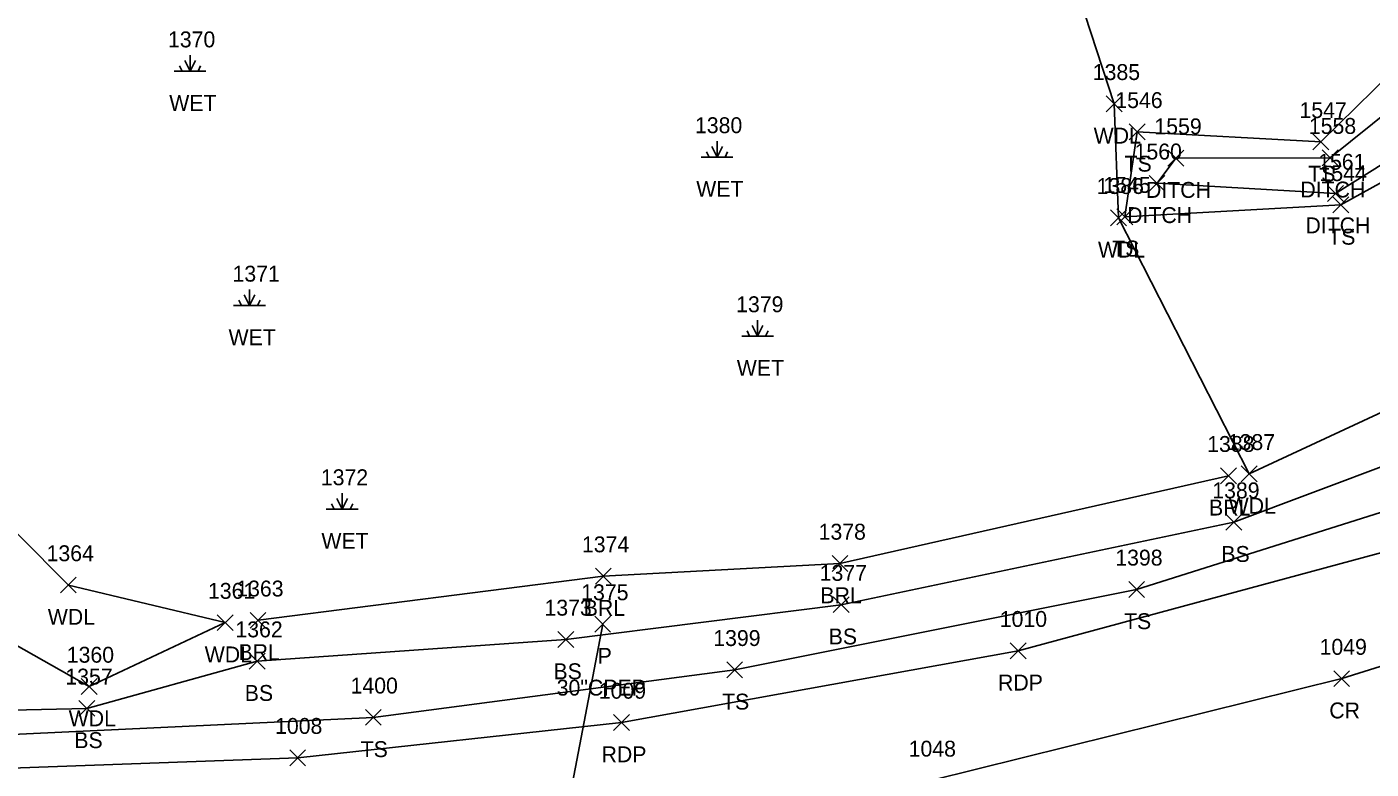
# Model space of a CAD drawing. Extents: x 1633660 to 1636532, y 388643 to 392631.
# Drawn here: x 1633906 to 1634075.1, y 388782.5 to 388875.9 of the extents above; entities that cross this region are included whole.
import ezdxf

# ---------------------------------------------------------------- set-up
doc = ezdxf.new("R2010")
doc.units = 0
for name, color, linetype in [('D_A', 7, 'Continuous'), ('D_C', 7, 'Continuous'), ('D_I', 7, 'Continuous'), ('D_TIC', 7, 'Continuous'), ('DCP', 7, 'Continuous'), ('DD', 7, 'Continuous'), ('L_A', 7, 'Continuous'), ('L_I', 7, 'Continuous'), ('L_TIC', 7, 'Continuous'), ('LABL', 7, 'Continuous'), ('LAWA', 7, 'Continuous'), ('LELB', 7, 'Continuous'), ('LWET', 7, 'Continuous'), ('P_A', 7, 'Continuous'), ('P_I', 7, 'Continuous'), ('P_TIC', 7, 'Continuous'), ('PET', 7, 'Continuous'), ('PRC', 7, 'Continuous')]:
    doc.layers.add(name, color=color, linetype=linetype)

msp = doc.modelspace()

# ---------------------------------------------------------------- linework, layer by layer
at = {"layer": 'D_TIC'}
for points in [[(1634049.51, 388858.37), (1634051.51, 388860.37)], [(1634051.51, 388858.37), (1634049.51, 388860.37)], [(1634068.93, 388858.42), (1634070.93, 388860.42)], [(1634070.93, 388858.42), (1634068.93, 388860.42)], [(1634047.14, 388855.2), (1634049.14, 388857.2)], [(1634049.14, 388855.2), (1634047.14, 388857.2)], [(1634069.58, 388853.91), (1634071.58, 388855.91)], [(1634071.58, 388853.91), (1634069.58, 388855.91)], [(1633977.41, 388799.74), (1633979.41, 388801.74)], [(1633979.41, 388799.74), (1633977.41, 388801.74)]]:
    msp.add_lwpolyline(points, dxfattribs=at)
at = {"layer": 'DCP'}
msp.add_lwpolyline([(1633978.41, 388800.74), (1633967.31, 388742.59)], dxfattribs=at)
at = {"layer": 'DD'}
msp.add_lwpolyline([(1634140.31, 388919.4), (1634122.83, 388893.99), (1634093.48, 388880.29), (1634083.12, 388870.01), (1634069.93, 388859.42), (1634050.51, 388859.37), (1634048.14, 388856.2), (1634070.58, 388854.91), (1634088.81, 388866.37), (1634110.94, 388881.74), (1634127.84, 388889.81), (1634143.36, 388916.71)], dxfattribs=at)
at = {"layer": 'L_TIC'}
for points in [[(1634041.75, 388865.2), (1634043.75, 388867.2)], [(1634043.75, 388865.2), (1634041.75, 388867.2)], [(1634044.65, 388861.67), (1634046.65, 388863.67)], [(1634046.65, 388861.67), (1634044.65, 388863.67)], [(1634067.75, 388860.41), (1634069.75, 388862.41)], [(1634069.75, 388860.41), (1634067.75, 388862.41)], [(1634070.27, 388852.48), (1634072.27, 388854.48)], [(1634072.27, 388852.48), (1634070.27, 388854.48)], [(1634042.29, 388850.86), (1634044.29, 388852.86)], [(1634044.29, 388850.86), (1634042.29, 388852.86)], [(1634043.09, 388850.99), (1634045.09, 388852.99)], [(1634045.09, 388850.99), (1634043.09, 388852.99)], [(1634056.14, 388818.4), (1634058.14, 388820.4)], [(1634058.14, 388818.4), (1634056.14, 388820.4)], [(1634058.73, 388818.64), (1634060.73, 388820.64)], [(1634060.73, 388818.64), (1634058.73, 388820.64)], [(1634056.79, 388812.56), (1634058.79, 388814.56)], [(1634058.79, 388812.56), (1634056.79, 388814.56)], [(1634007.26, 388807.36), (1634009.26, 388809.36)], [(1634009.26, 388807.36), (1634007.26, 388809.36)], [(1633977.49, 388805.77), (1633979.49, 388807.77)], [(1633979.49, 388805.77), (1633977.49, 388807.77)], [(1633910.2, 388804.65), (1633912.2, 388806.65)], [(1633912.2, 388804.65), (1633910.2, 388806.65)], [(1634044.58, 388804.1), (1634046.58, 388806.1)], [(1634046.58, 388804.1), (1634044.58, 388806.1)], [(1634007.4, 388802.18), (1634009.4, 388804.18)], [(1634009.4, 388802.18), (1634007.4, 388804.18)], [(1633929.93, 388799.92), (1633931.93, 388801.92)], [(1633931.93, 388799.92), (1633929.93, 388801.92)], [(1633934.06, 388800.21), (1633936.06, 388802.21)], [(1633936.06, 388800.21), (1633934.06, 388802.21)], [(1633972.78, 388797.8), (1633974.78, 388799.8)], [(1633974.78, 388797.8), (1633972.78, 388799.8)], [(1633933.95, 388795.07), (1633935.95, 388797.07)], [(1633935.95, 388795.07), (1633933.95, 388797.07)], [(1633994.02, 388793.98), (1633996.02, 388795.98)], [(1633996.02, 388793.98), (1633994.02, 388795.98)], [(1633912.82, 388791.88), (1633914.82, 388793.88)], [(1633914.82, 388791.88), (1633912.82, 388793.88)], [(1633912.51, 388789.13), (1633914.51, 388791.13)], [(1633914.51, 388789.13), (1633912.51, 388791.13)], [(1633948.56, 388788), (1633950.56, 388790)], [(1633950.56, 388788), (1633948.56, 388790)]]:
    msp.add_lwpolyline(points, dxfattribs=at)
at = {"layer": 'LABL'}
msp.add_lwpolyline([(1633935.06, 388801.21), (1633978.49, 388806.77), (1634008.26, 388808.36), (1634057.14, 388819.4)], dxfattribs=at)
at = {"layer": 'LAWA'}
for points in [[(1634029.51, 388906.75), (1634042.75, 388866.2), (1634043.29, 388851.86), (1634059.73, 388819.64), (1634086.07, 388831.91), (1634132.5, 388845.49), (1634141.64, 388844.49), (1634171.78, 388858.91), (1634210.32, 388873.4), (1634220.65, 388882.43), (1634241.67, 388885.4), (1634275.37, 388895.77), (1634312.68, 388911.32), (1634346.59, 388927.34), (1634362.7, 388937.8), (1634391.49, 388949.24), (1634419.55, 388956.24), (1634431.93, 388958.02)], [(1633871.87, 388818.29), (1633885.15, 388797.47), (1633895.12, 388803.46), (1633913.82, 388792.88), (1633930.93, 388800.92), (1633911.2, 388805.65), (1633898.58, 388818.29), (1633885.23, 388835.61), (1633885.66, 388866.72), (1633887.99, 388896.34)]]:
    msp.add_lwpolyline(points, dxfattribs=at)
at = {"layer": 'LELB'}
for points in [[(1634144.21, 388912.2), (1634135.78, 388896.22), (1634121.93, 388881.1), (1634093.91, 388866), (1634071.27, 388853.48), (1634044.09, 388851.99), (1634045.65, 388862.67), (1634068.75, 388861.41), (1634082.09, 388874.51), (1634092.19, 388884.76), (1634120.03, 388895.98), (1634133.03, 388917.32)], [(1633865.46, 388809.99), (1633877.4, 388789.31), (1633913.51, 388790.13), (1633934.95, 388796.07), (1633973.78, 388798.8), (1634008.4, 388803.18), (1634057.79, 388813.56), (1634087.95, 388824.89), (1634134.34, 388843.13)], [(1634140.78, 388840.91), (1634131.75, 388832.34), (1634088.08, 388818.52), (1634045.58, 388805.1), (1633995.02, 388794.98), (1633949.56, 388789), (1633902.34, 388786.74), (1633874.08, 388786.77)]]:
    msp.add_lwpolyline(points, dxfattribs=at)
at = {"layer": 'LWET'}
for p, q in [((1633926.51, 388870.31), (1633926.51, 388872.31)), ((1633928.51, 388870.31), (1633924.51, 388870.31)), ((1633925.51, 388870.31), (1633925.18, 388870.98)), ((1633926.51, 388870.31), (1633925.84, 388871.64)), ((1633926.51, 388870.31), (1633927.18, 388871.64)), ((1633927.51, 388870.31), (1633927.84, 388870.98)), ((1633991.8, 388859.51), (1633991.47, 388860.18)), ((1633992.8, 388859.51), (1633992.13, 388860.84)), ((1633992.8, 388859.51), (1633992.8, 388861.51)), ((1633992.8, 388859.51), (1633993.47, 388860.84)), ((1633993.8, 388859.51), (1633994.13, 388860.18)), ((1633994.8, 388859.51), (1633990.8, 388859.51)), ((1633932.98, 388840.83), (1633932.64, 388841.5)), ((1633933.98, 388840.83), (1633933.31, 388842.17)), ((1633933.98, 388840.83), (1633933.98, 388842.83)), ((1633933.98, 388840.83), (1633934.64, 388842.17)), ((1633934.98, 388840.83), (1633935.31, 388841.5)), ((1633935.98, 388840.83), (1633931.98, 388840.83)), ((1633997.9, 388836.98), (1633997.23, 388838.32)), ((1633997.9, 388836.98), (1633997.9, 388838.98)), ((1633997.9, 388836.98), (1633998.57, 388838.32)), ((1633999.9, 388836.98), (1633995.9, 388836.98)), ((1633996.9, 388836.98), (1633996.57, 388837.65)), ((1633998.9, 388836.98), (1633999.23, 388837.65)), ((1633945.65, 388815.21), (1633944.98, 388816.54)), ((1633945.65, 388815.21), (1633945.65, 388817.21)), ((1633945.65, 388815.21), (1633946.32, 388816.54)), ((1633947.65, 388815.21), (1633943.65, 388815.21)), ((1633944.65, 388815.21), (1633944.32, 388815.87)), ((1633946.65, 388815.21), (1633946.98, 388815.87))]:
    msp.add_line(p, q, dxfattribs=at)
at = {"layer": 'P_TIC'}
for points in [[(1634029.66, 388796.38), (1634031.66, 388798.38)], [(1634031.66, 388796.38), (1634029.66, 388798.38)], [(1634070.37, 388792.87), (1634072.37, 388794.87)], [(1634072.37, 388792.87), (1634070.37, 388794.87)], [(1633979.78, 388787.35), (1633981.78, 388789.35)], [(1633981.78, 388787.35), (1633979.78, 388789.35)], [(1633939.05, 388782.92), (1633941.05, 388784.92)], [(1633941.05, 388782.92), (1633939.05, 388784.92)]]:
    msp.add_lwpolyline(points, dxfattribs=at)
at = {"layer": 'PET'}
msp.add_lwpolyline([(1633681.12, 388754.49), (1633725.19, 388768.3), (1633776.36, 388776.79), (1633828.74, 388780.84), (1633883.05, 388781.87), (1633940.05, 388783.92), (1633980.78, 388788.35), (1634030.66, 388797.38), (1634082.16, 388811.29), (1634131.93, 388828.18), (1634182.59, 388846.73), (1634235.61, 388867.86)], dxfattribs=at)
at = {"layer": 'PRC'}
msp.add_lwpolyline([(1633685.21, 388740.89), (1633722.47, 388753.09), (1633765.95, 388761.74), (1633808.84, 388766.45), (1633860.63, 388768.05), (1633911.93, 388769.08), (1633965.45, 388772.58), (1634019.68, 388781.06), (1634071.37, 388793.87), (1634111.14, 388806.36), (1634160.92, 388824.06), (1634207.93, 388842.02), (1634253.71, 388860.36), (1634302.74, 388880.25), (1634347.86, 388899.14), (1634390.05, 388916.89), (1634425.6, 388933.8), (1634443.27, 388943.77), (1634464.46, 388957.57)], dxfattribs=at)

# ---------------------------------------------------------------- texts
at = {"layer": 'D_A'}
for s, p in [('DITCH', (1634046.75, 388854.37)), ('DITCH', (1634066.17, 388854.42)), ('DITCH', (1634044.38, 388851.2)), ('DITCH', (1634066.81, 388849.91)), ('P', (1633977.78, 388795.74))]:
    msp.add_text(s, height=2, dxfattribs=at).set_placement(p)
at = {"layer": 'D_C'}
msp.add_text('30"CPEP', height=2, dxfattribs=at).set_placement((1633972.63, 388791.74))
at = {"layer": 'D_I'}
for s, p in [('1559', (1634047.81, 388862.37)), ('1558', (1634067.24, 388862.42)), ('1560', (1634045.32, 388859.2)), ('1561', (1634068.41, 388857.91)), ('1375', (1633975.71, 388803.74))]:
    msp.add_text(s, height=2, dxfattribs=at).set_placement(p)
at = {"layer": 'L_A'}
for s, p in [('WET', (1633923.89, 388865.31)), ('WDL', (1634040.17, 388861.2)), ('TS', (1634044.06, 388857.67)), ('TS', (1634067.16, 388856.41)), ('WET', (1633990.18, 388854.51)), ('TS', (1634069.68, 388848.48)), ('WDL', (1634040.71, 388846.86)), ('TS', (1634042.5, 388846.99)), ('WET', (1633931.35, 388835.83)), ('WET', (1633995.28, 388831.98)), ('BRL', (1634054.68, 388814.4)), ('WDL', (1634057.15, 388814.64)), ('WET', (1633943.03, 388810.21)), ('BS', (1634056.23, 388808.56)), ('BRL', (1634005.8, 388803.36)), ('WDL', (1633908.61, 388800.65)), ('BRL', (1633976.03, 388801.77)), ('TS', (1634043.99, 388800.1)), ('BS', (1634006.84, 388798.18)), ('WDL', (1633928.35, 388795.92)), ('BRL', (1633932.6, 388796.21)), ('BS', (1633972.22, 388793.8)), ('BS', (1633933.39, 388791.07)), ('TS', (1633993.43, 388789.98)), ('WDL', (1633911.24, 388787.88)), ('BS', (1633911.95, 388785.13)), ('TS', (1633947.97, 388784))]:
    msp.add_text(s, height=2, dxfattribs=at).set_placement(p)
at = {"layer": 'L_I'}
for s, p in [('1370', (1633923.73, 388873.31)), ('1385', (1634040.06, 388869.2)), ('1546', (1634042.9, 388865.67)), ('1547', (1634066.06, 388864.41)), ('1380', (1633990.02, 388862.51)), ('1544', (1634068.58, 388856.48)), ('1386', (1634040.54, 388854.86)), ('1545', (1634041.4, 388854.99)), ('1371', (1633931.85, 388843.83)), ('1379', (1633995.2, 388839.98)), ('1388', (1634054.45, 388822.4)), ('1387', (1634057.04, 388822.64)), ('1372', (1633942.96, 388818.21)), ('1389', (1634055.09, 388816.56)), ('1378', (1634005.57, 388811.36)), ('1374', (1633975.8, 388809.77)), ('1364', (1633908.46, 388808.65)), ('1398', (1634042.89, 388808.1)), ('1377', (1634005.71, 388806.18)), ('1361', (1633928.76, 388803.92)), ('1363', (1633932.32, 388804.21)), ('1373', (1633971.09, 388801.8)), ('1362', (1633932.21, 388799.07)), ('1399', (1633992.32, 388797.98)), ('1360', (1633911, 388795.88)), ('1357', (1633910.82, 388793.13)), ('1400', (1633946.7, 388792))]:
    msp.add_text(s, height=2, dxfattribs=at).set_placement(p)
at = {"layer": 'P_A'}
for s, p in [('RDP', (1634028.14, 388792.38)), ('CR', (1634069.81, 388788.87)), ('RDP', (1633978.27, 388783.35))]:
    msp.add_text(s, height=2, dxfattribs=at).set_placement(p)
at = {"layer": 'P_I'}
for s, p in [('1010', (1634028.36, 388800.38)), ('1049', (1634068.59, 388796.87)), ('1009', (1633977.92, 388791.35)), ('1008', (1633937.2, 388786.92)), ('1048', (1634016.9, 388784.06))]:
    msp.add_text(s, height=2, dxfattribs=at).set_placement(p)

doc.saveas('drawing.dxf')
